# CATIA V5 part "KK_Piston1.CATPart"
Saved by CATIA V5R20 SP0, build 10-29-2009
Part number: Piston1
Bounding box of the stored display mesh (mm): x -43.546 to -15.004, y 56.538 to 81.653, z 33.935 to 105
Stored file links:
  G:\Khaled_CFAO_2011\ST2M\ST2M_GR1\msallin\Khaled\Version_Finale\KK_Piston1.CATPart
  C:\Users\Mathieu\Desktop\Think Motion\JOUG-MELEE2.CATProduct
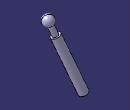
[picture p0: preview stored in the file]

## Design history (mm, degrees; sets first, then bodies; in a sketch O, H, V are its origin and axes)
External parameters (linked from other documents)
  `External.Taille du joug` = 100 mm
Set1
  Line1: linked copy from another document
  Line2: linked copy from another document
  Point1: linked copy from another document
  Point2: linked copy from another document
Set2
  Plane1: type 2Lines, Element1 Line1, Element2 Line2
Body1 (main body)
  Sketch1 on Plane1, origin (-0.277, 81.5078, 20.3771), H (-1, -0.0034, 0), V (0.0008, -0.2425, 0.9701)
    point P1 (39.2893, 15.5418)
    line L1 (39.2893, 15.5418) -> (43.2878, 16.7136)
    line L2 (43.2878, 16.7136) -> (27.8193, 69.4936)
    line L3 (27.8193, 69.4936) -> (26.2199, 69.0248)
    line L4 (26.2199, 69.0248) -> (23.4075, 78.6212)
    point P5 (23.4075, 78.6212)
    arc A1 centre (19.7906, 82.0734) radius 5 from (23.4075, 78.6212) to (18.3843, 86.8716) ccw
    point P6 (19.7906, 82.0734)
    point P7 (23.4075, 78.6212)
    point P8 (18.3843, 86.8716)
    reference projected line E1 (19.7906, 82.0734) -> (50, -21.0042) from Line2
    reference projected line E2 (19.7906, 82.0734) -> (50, -21.0042) from Line2
    reference projected line E3 (19.7906, 82.0734) -> (50, -21.0042) from Line2
    reference projected line E4 (19.7906, 82.0734) -> (50, -21.0042) from Line2
    reference projected point E5 (19.7906, 82.0734) from Point2
    reference projected line E6 (19.7906, 82.0734) -> (50, -21.0042) from Line2
    distance P1 E1 = 0
    length L2 = 55 {= `External.Taille du joug` *(7/10-1/10-1/20)}
    distance L2 E3 = 4.1667 {= `External.Taille du joug` /24}
    length L4 = 10 {= `External.Taille du joug` /10}
    distance L4 E4 = 2.5 {= `External.Taille du joug` /40}
    distance E5 P6 = 0
    radius A1 = 5 {= `External.Taille du joug` /20}
    distance P8 E6 = 0
    perpendicularity: L2 L1
    parallelism: L3 L1, L4 L2
    coincidence: P5 P7, E2 P6
  Shaft1: profile Sketch1, axis Line2, angle 360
